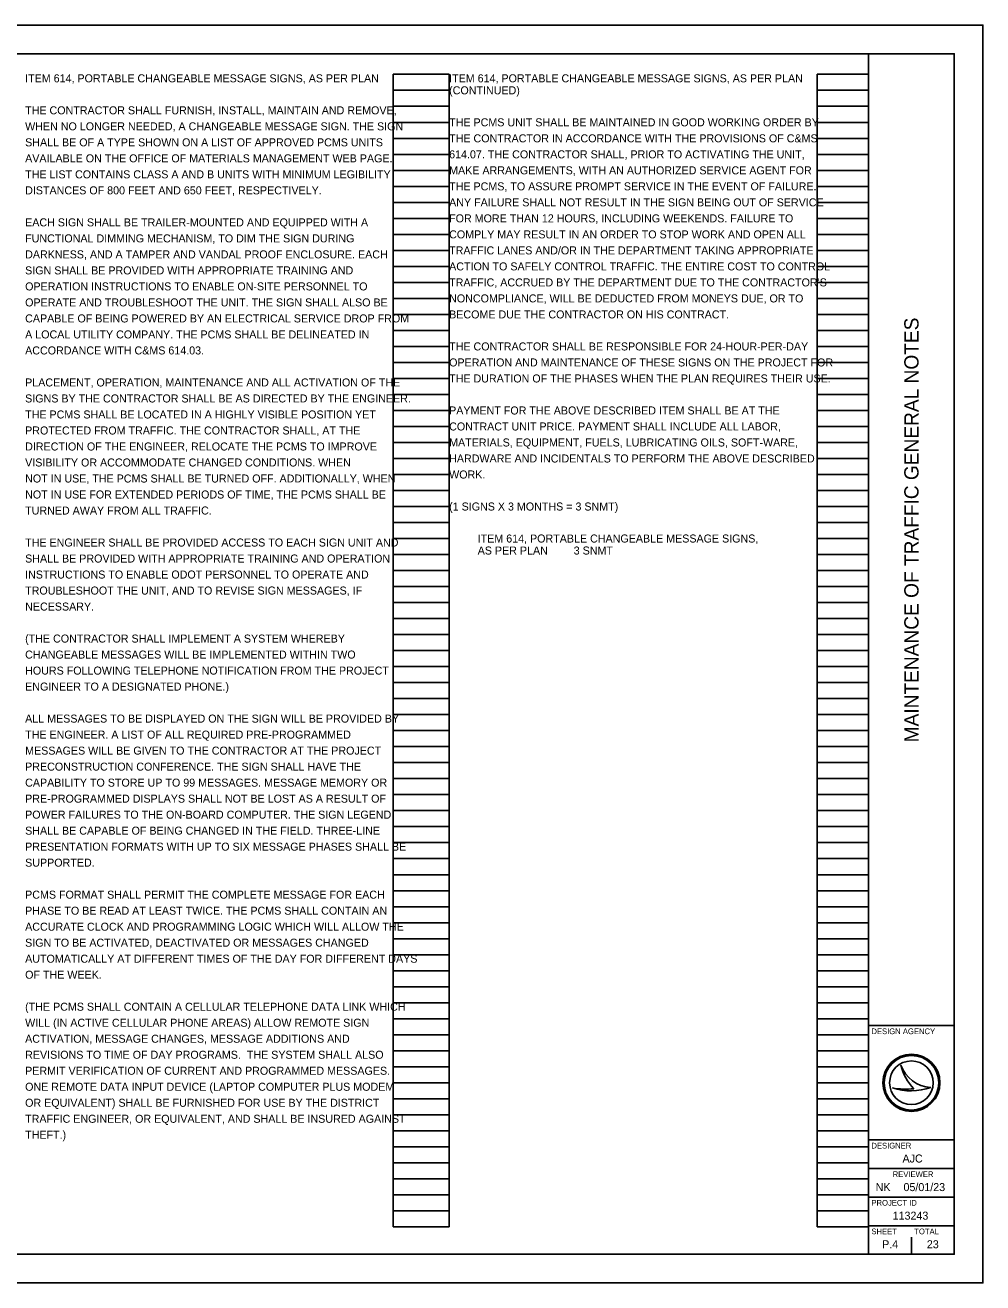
# Model space of a CAD drawing. Extents: x 0 to 34, y 0 to 22.
# Drawn here: x 17.24 to 34, y 0 to 22 of the extents above; entities that cross this region are included whole.
import ezdxf

# ---------------------------------------------------------------- set-up
doc = ezdxf.new("R2010")
doc.units = 0
for name, color, linetype in [('SH_Border', 7, 'Continuous'), ('SH_Cut_Line', 7, 'Continuous'), ('SH_Data', 7, 'Continuous'), ('SH_Text', 7, 'Continuous')]:
    doc.layers.add(name, color=color, linetype=linetype)

msp = doc.modelspace()

# ---------------------------------------------------------------- linework, layer by layer
at = {"layer": 'SH_Border'}
for p, q in [((32, 0.5), (32, 21.5)), ((32, 4.5), (33.5, 4.5)), ((32, 2.5), (33.5, 2.5)), ((32, 2), (33.5, 2)), ((32, 1.5), (33.5, 1.5)), ((32, 1), (33.5, 1))]:
    msp.add_line(p, q, dxfattribs=at)
msp.add_lwpolyline([(1.5, 21.5), (33.5, 21.5), (33.5, 0.5), (1.5, 0.5)], close=True, dxfattribs=at)
at = {"layer": 'SH_Cut_Line'}
msp.add_lwpolyline([(0, 0), (34, 0), (34, 22), (0, 22)], close=True, dxfattribs=at)
at = {"layer": 'SH_Data'}
for p, q in [((23.68, 0.98), (23.68, 21.14)), ((23.68, 21.14), (24.66, 21.14)), ((24.66, 0.98), (24.66, 21.14)), ((31.1, 0.98), (31.1, 21.14)), ((31.1, 21.14), (32, 21.14)), ((32, 0.98), (32, 21.14)), ((23.68, 20.86), (24.66, 20.86)), ((31.1, 20.86), (32, 20.86)), ((23.68, 20.58), (24.66, 20.58)), ((31.1, 20.58), (32, 20.58)), ((23.68, 20.3), (24.66, 20.3)), ((31.1, 20.3), (32, 20.3)), ((23.68, 20.02), (24.66, 20.02)), ((31.1, 20.02), (32, 20.02)), ((23.68, 19.74), (24.66, 19.74)), ((31.1, 19.74), (32, 19.74)), ((23.68, 19.46), (24.66, 19.46)), ((31.1, 19.46), (32, 19.46)), ((23.68, 19.18), (24.66, 19.18)), ((31.1, 19.18), (32, 19.18)), ((23.68, 18.9), (24.66, 18.9)), ((31.1, 18.9), (32, 18.9)), ((23.68, 18.62), (24.66, 18.62)), ((31.1, 18.62), (32, 18.62)), ((23.68, 18.34), (24.66, 18.34)), ((31.1, 18.34), (32, 18.34)), ((23.68, 18.06), (24.66, 18.06)), ((31.1, 18.06), (32, 18.06)), ((23.68, 17.78), (24.66, 17.78)), ((31.1, 17.78), (32, 17.78)), ((23.68, 17.5), (24.66, 17.5)), ((31.1, 17.5), (32, 17.5)), ((23.68, 17.22), (24.66, 17.22)), ((31.1, 17.22), (32, 17.22)), ((23.68, 16.94), (24.66, 16.94)), ((31.1, 16.94), (32, 16.94)), ((23.68, 16.66), (24.66, 16.66)), ((31.1, 16.66), (32, 16.66)), ((23.68, 16.38), (24.66, 16.38)), ((31.1, 16.38), (32, 16.38)), ((23.68, 16.1), (24.66, 16.1)), ((31.1, 16.1), (32, 16.1)), ((23.68, 15.82), (24.66, 15.82)), ((31.1, 15.82), (32, 15.82)), ((23.68, 15.54), (24.66, 15.54)), ((31.1, 15.54), (32, 15.54)), ((23.68, 15.26), (24.66, 15.26)), ((31.1, 15.26), (32, 15.26)), ((23.68, 14.98), (24.66, 14.98)), ((31.1, 14.98), (32, 14.98)), ((23.68, 14.7), (24.66, 14.7)), ((31.1, 14.7), (32, 14.7)), ((23.68, 14.42), (24.66, 14.42)), ((31.1, 14.42), (32, 14.42)), ((23.68, 14.14), (24.66, 14.14)), ((31.1, 14.14), (32, 14.14)), ((23.68, 13.86), (24.66, 13.86)), ((31.1, 13.86), (32, 13.86)), ((23.68, 13.58), (24.66, 13.58)), ((31.1, 13.58), (32, 13.58)), ((23.68, 13.3), (24.66, 13.3)), ((31.1, 13.3), (32, 13.3)), ((23.68, 13.02), (24.66, 13.02)), ((31.1, 13.02), (32, 13.02)), ((23.68, 12.74), (24.66, 12.74)), ((31.1, 12.74), (32, 12.74)), ((23.68, 12.46), (24.66, 12.46)), ((31.1, 12.46), (32, 12.46)), ((23.68, 12.18), (24.66, 12.18)), ((31.1, 12.18), (32, 12.18)), ((23.68, 11.9), (24.66, 11.9)), ((31.1, 11.9), (32, 11.9)), ((23.68, 11.62), (24.66, 11.62)), ((31.1, 11.62), (32, 11.62)), ((23.68, 11.34), (24.66, 11.34)), ((31.1, 11.34), (32, 11.34)), ((23.68, 11.06), (24.66, 11.06)), ((31.1, 11.06), (32, 11.06)), ((23.68, 10.78), (24.66, 10.78)), ((31.1, 10.78), (32, 10.78)), ((23.68, 10.5), (24.66, 10.5)), ((31.1, 10.5), (32, 10.5)), ((23.68, 10.22), (24.66, 10.22)), ((31.1, 10.22), (32, 10.22)), ((23.68, 9.94), (24.66, 9.94)), ((31.1, 9.94), (32, 9.94)), ((23.68, 9.66), (24.66, 9.66)), ((31.1, 9.66), (32, 9.66)), ((23.68, 9.38), (24.66, 9.38)), ((31.1, 9.38), (32, 9.38)), ((23.68, 9.1), (24.66, 9.1)), ((31.1, 9.1), (32, 9.1)), ((23.68, 8.82), (24.66, 8.82)), ((31.1, 8.82), (32, 8.82)), ((23.68, 8.54), (24.66, 8.54)), ((31.1, 8.54), (32, 8.54)), ((23.68, 8.26), (24.66, 8.26)), ((31.1, 8.26), (32, 8.26)), ((23.68, 7.98), (24.66, 7.98)), ((31.1, 7.98), (32, 7.98)), ((23.68, 7.7), (24.66, 7.7)), ((31.1, 7.7), (32, 7.7)), ((23.68, 7.42), (24.66, 7.42)), ((31.1, 7.42), (32, 7.42)), ((23.68, 7.14), (24.66, 7.14)), ((31.1, 7.14), (32, 7.14)), ((23.68, 6.86), (24.66, 6.86)), ((31.1, 6.86), (32, 6.86)), ((23.68, 6.58), (24.66, 6.58)), ((31.1, 6.58), (32, 6.58)), ((23.68, 6.3), (24.66, 6.3)), ((31.1, 6.3), (32, 6.3)), ((23.68, 6.02), (24.66, 6.02)), ((31.1, 6.02), (32, 6.02)), ((23.68, 5.74), (24.66, 5.74)), ((31.1, 5.74), (32, 5.74)), ((23.68, 5.46), (24.66, 5.46)), ((31.1, 5.46), (32, 5.46)), ((23.68, 5.18), (24.66, 5.18)), ((31.1, 5.18), (32, 5.18)), ((23.68, 4.9), (24.66, 4.9)), ((31.1, 4.9), (32, 4.9)), ((23.68, 4.62), (24.66, 4.62)), ((31.1, 4.62), (32, 4.62)), ((23.68, 4.34), (24.66, 4.34)), ((31.1, 4.34), (32, 4.34)), ((23.68, 4.06), (24.66, 4.06)), ((31.1, 4.06), (32, 4.06)), ((23.68, 3.78), (24.66, 3.78)), ((31.1, 3.78), (32, 3.78)), ((32.567, 3.81), (32.567, 3.81)), ((23.68, 3.5), (24.66, 3.5)), ((31.1, 3.5), (32, 3.5)), ((32.417, 3.41), (32.417, 3.41)), ((32.75, 3.5), (32.75, 3.5)), ((33.087, 3.419), (33.087, 3.419)), ((23.68, 3.22), (24.66, 3.22)), ((31.1, 3.22), (32, 3.22)), ((23.68, 2.94), (24.66, 2.94)), ((31.1, 2.94), (32, 2.94)), ((23.68, 2.66), (24.66, 2.66)), ((31.1, 2.66), (32, 2.66)), ((23.68, 2.38), (24.66, 2.38)), ((31.1, 2.38), (32, 2.38)), ((23.68, 2.1), (24.66, 2.1)), ((31.1, 2.1), (32, 2.1)), ((23.68, 1.82), (24.66, 1.82)), ((31.1, 1.82), (32, 1.82)), ((23.68, 1.54), (24.66, 1.54)), ((31.1, 1.54), (32, 1.54)), ((23.68, 1.26), (24.66, 1.26)), ((31.1, 1.26), (32, 1.26)), ((23.68, 0.98), (24.66, 0.98)), ((31.1, 0.98), (32, 0.98)), ((32.375, 0.675), (32.375, 0.675)), ((32.75, 0.5), (32.75, 0.8))]:
    msp.add_line(p, q, dxfattribs=at)
for radius in [0.5, 0.477, 0.477, 0.382]:
    msp.add_circle((32.75, 3.5), radius, dxfattribs=at)
for centre, radius, start, end in [((33.116, 3.998), 0.58, 198.9257, 198.9319), ((33.347, 3.97), 0.796, 191.6379, 191.6421), ((33.116, 3.998), 0.58, 198.9319, 267.1657), ((33.347, 3.97), 0.796, 191.6421, 226.0947), ((32.739, 4.37), 1.013, 251.4576, 290.0832), ((32.648, 4.654), 1.266, 259.4964, 259.4995), ((32.739, 4.37), 1.013, 251.4527, 251.4576), ((32.648, 4.654), 1.266, 259.4995, 276.6672)]:
    msp.add_arc(centre, radius, start, end, dxfattribs=at)

# ---------------------------------------------------------------- texts
msp.add_text('MAINTENANCE OF TRAFFIC GENERAL NOTES', height=0.25, rotation=90, dxfattribs=at).set_placement((32.875, 9.455))
for s, height, p in [('DESIGN AGENCY', 0.1, (32.05, 4.35)), ('DESIGNER', 0.1, (32.05, 2.35)), ('AJC', 0.14, (32.594, 2.105)), ('REVIEWER', 0.1, (32.422, 1.85)), ('NK', 0.14, (32.124, 1.605)), ('05/01/23', 0.14, (32.611, 1.605)), ('PROJECT ID', 0.1, (32.05, 1.35)), ('113243', 0.14, (32.421, 1.105)), ('SHEET', 0.1, (32.05, 0.85)), ('TOTAL', 0.1, (32.8, 0.85)), ('P.4', 0.14, (32.237, 0.605)), ('23', 0.14, (33.02, 0.605))]:
    msp.add_text(s, height=height, dxfattribs=at).set_placement(p)
at = {"layer": 'SH_Text'}
for s, p in [('ITEM 614, PORTABLE CHANGEABLE MESSAGE SIGNS, AS PER PLAN', (17.24, 21)), ('ITEM 614, PORTABLE CHANGEABLE MESSAGE SIGNS, AS PER PLAN', (24.66, 21)), ('(CONTINUED)', (24.66, 20.79)), ('THE CONTRACTOR SHALL FURNISH, INSTALL, MAINTAIN AND REMOVE, ', (17.24, 20.44)), ('WHEN NO LONGER NEEDED, A CHANGEABLE MESSAGE SIGN. THE SIGN ', (17.24, 20.16)), ('THE PCMS UNIT SHALL BE MAINTAINED IN GOOD WORKING ORDER BY ', (24.66, 20.23)), ('SHALL BE OF A TYPE SHOWN ON A LIST OF APPROVED PCMS UNITS ', (17.24, 19.88)), ('THE CONTRACTOR IN ACCORDANCE WITH THE PROVISIONS OF C&MS ', (24.66, 19.95)), ('614.07. THE CONTRACTOR SHALL, PRIOR TO ACTIVATING THE UNIT, ', (24.66, 19.67)), ('AVAILABLE ON THE OFFICE OF MATERIALS MANAGEMENT WEB PAGE. ', (17.24, 19.6)), ('THE LIST CONTAINS CLASS A AND B UNITS WITH MINIMUM LEGIBILITY ', (17.24, 19.32)), ('MAKE ARRANGEMENTS, WITH AN AUTHORIZED SERVICE AGENT FOR ', (24.66, 19.39)), ('DISTANCES OF 800 FEET AND 650 FEET, RESPECTIVELY.', (17.24, 19.04)), ('THE PCMS, TO ASSURE PROMPT SERVICE IN THE EVENT OF FAILURE. ', (24.66, 19.11)), ('ANY FAILURE SHALL NOT RESULT IN THE SIGN BEING OUT OF SERVICE ', (24.66, 18.83)), ('EACH SIGN SHALL BE TRAILER-MOUNTED AND EQUIPPED WITH A ', (17.24, 18.48)), ('FOR MORE THAN 12 HOURS, INCLUDING WEEKENDS. FAILURE TO ', (24.66, 18.55)), ('FUNCTIONAL DIMMING MECHANISM, TO DIM THE SIGN DURING ', (17.24, 18.2)), ('COMPLY MAY RESULT IN AN ORDER TO STOP WORK AND OPEN ALL ', (24.66, 18.27)), ('DARKNESS, AND A TAMPER AND VANDAL PROOF ENCLOSURE. EACH ', (17.24, 17.92)), ('TRAFFIC LANES AND/OR IN THE DEPARTMENT TAKING APPROPRIATE ', (24.66, 17.99)), ('ACTION TO SAFELY CONTROL TRAFFIC. THE ENTIRE COST TO CONTROL ', (24.66, 17.71)), ('SIGN SHALL BE PROVIDED WITH APPROPRIATE TRAINING AND ', (17.24, 17.64)), ('OPERATION INSTRUCTIONS TO ENABLE ON-SITE PERSONNEL TO ', (17.24, 17.36)), ("TRAFFIC, ACCRUED BY THE DEPARTMENT DUE TO THE CONTRACTOR'S", (24.66, 17.43)), ('OPERATE AND TROUBLESHOOT THE UNIT. THE SIGN SHALL ALSO BE ', (17.24, 17.08)), ('NONCOMPLIANCE, WILL BE DEDUCTED FROM MONEYS DUE, OR TO ', (24.66, 17.15)), ('CAPABLE OF BEING POWERED BY AN ELECTRICAL SERVICE DROP FROM ', (17.24, 16.8)), ('BECOME DUE THE CONTRACTOR ON HIS CONTRACT.', (24.66, 16.87)), ('A LOCAL UTILITY COMPANY. THE PCMS SHALL BE DELINEATED IN ', (17.24, 16.52)), ('ACCORDANCE WITH C&MS 614.03.', (17.24, 16.24)), ('THE CONTRACTOR SHALL BE RESPONSIBLE FOR 24-HOUR-PER-DAY ', (24.66, 16.31)), ('OPERATION AND MAINTENANCE OF THESE SIGNS ON THE PROJECT FOR ', (24.66, 16.03)), ('THE DURATION OF THE PHASES WHEN THE PLAN REQUIRES THEIR USE.', (24.66, 15.75)), ('PLACEMENT, OPERATION, MAINTENANCE AND ALL ACTIVATION OF THE ', (17.24, 15.68)), ('SIGNS BY THE CONTRACTOR SHALL BE AS DIRECTED BY THE ENGINEER. ', (17.24, 15.4)), ('THE PCMS SHALL BE LOCATED IN A HIGHLY VISIBLE POSITION YET ', (17.24, 15.12)), ('PAYMENT FOR THE ABOVE DESCRIBED ITEM SHALL BE AT THE ', (24.66, 15.19)), ('PROTECTED FROM TRAFFIC. THE CONTRACTOR SHALL, AT THE ', (17.24, 14.84)), ('CONTRACT UNIT PRICE. PAYMENT SHALL INCLUDE ALL LABOR, ', (24.66, 14.91)), ('MATERIALS, EQUIPMENT, FUELS, LUBRICATING OILS, SOFT-WARE, ', (24.66, 14.63)), ('DIRECTION OF THE ENGINEER, RELOCATE THE PCMS TO IMPROVE', (17.24, 14.56)), ('VISIBILITY OR ACCOMMODATE CHANGED CONDITIONS. WHEN', (17.24, 14.28)), ('HARDWARE AND INCIDENTALS TO PERFORM THE ABOVE DESCRIBED ', (24.66, 14.35)), ('NOT IN USE, THE PCMS SHALL BE TURNED OFF. ADDITIONALLY, WHEN ', (17.24, 14)), ('WORK.', (24.66, 14.07)), ('NOT IN USE FOR EXTENDED PERIODS OF TIME, THE PCMS SHALL BE ', (17.24, 13.72)), ('(1 SIGNS X 3 MONTHS = 3 SNMT)', (24.66, 13.51)), ('TURNED AWAY FROM ALL TRAFFIC.', (17.24, 13.44)), ('THE ENGINEER SHALL BE PROVIDED ACCESS TO EACH SIGN UNIT AND ', (17.24, 12.88)), ('ITEM 614, PORTABLE CHANGEABLE MESSAGE SIGNS, ', (25.16, 12.95)), ('AS PER PLAN', (25.16, 12.74)), ('3 SNMT', (26.84, 12.74)), ('SHALL BE PROVIDED WITH APPROPRIATE TRAINING AND OPERATION ', (17.24, 12.6)), ('INSTRUCTIONS TO ENABLE ODOT PERSONNEL TO OPERATE AND ', (17.24, 12.32)), ('TROUBLESHOOT THE UNIT, AND TO REVISE SIGN MESSAGES, IF ', (17.24, 12.04)), ('NECESSARY.', (17.24, 11.76)), ('(THE CONTRACTOR SHALL IMPLEMENT A SYSTEM WHEREBY ', (17.24, 11.2)), ('CHANGEABLE MESSAGES WILL BE IMPLEMENTED WITHIN TWO', (17.24, 10.92)), ('HOURS FOLLOWING TELEPHONE NOTIFICATION FROM THE PROJECT ', (17.24, 10.64)), ('ENGINEER TO A DESIGNATED PHONE.)', (17.24, 10.36)), ('ALL MESSAGES TO BE DISPLAYED ON THE SIGN WILL BE PROVIDED BY ', (17.24, 9.8)), ('THE ENGINEER. A LIST OF ALL REQUIRED PRE-PROGRAMMED ', (17.24, 9.52)), ('MESSAGES WILL BE GIVEN TO THE CONTRACTOR AT THE PROJECT ', (17.24, 9.24)), ('PRECONSTRUCTION CONFERENCE. THE SIGN SHALL HAVE THE ', (17.24, 8.96)), ('CAPABILITY TO STORE UP TO 99 MESSAGES. MESSAGE MEMORY OR', (17.24, 8.68)), ('PRE-PROGRAMMED DISPLAYS SHALL NOT BE LOST AS A RESULT OF ', (17.24, 8.4)), ('POWER FAILURES TO THE ON-BOARD COMPUTER. THE SIGN LEGEND ', (17.24, 8.12)), ('SHALL BE CAPABLE OF BEING CHANGED IN THE FIELD. THREE-LINE ', (17.24, 7.84)), ('PRESENTATION FORMATS WITH UP TO SIX MESSAGE PHASES SHALL BE', (17.24, 7.56)), ('SUPPORTED.  ', (17.24, 7.28)), ('PCMS FORMAT SHALL PERMIT THE COMPLETE MESSAGE FOR EACH ', (17.24, 6.72)), ('PHASE TO BE READ AT LEAST TWICE. THE PCMS SHALL CONTAIN AN ', (17.24, 6.44)), ('ACCURATE CLOCK AND PROGRAMMING LOGIC WHICH WILL ALLOW THE ', (17.24, 6.16)), ('SIGN TO BE ACTIVATED, DEACTIVATED OR MESSAGES CHANGED', (17.24, 5.88)), ('AUTOMATICALLY AT DIFFERENT TIMES OF THE DAY FOR DIFFERENT DAYS ', (17.24, 5.6)), ('OF THE WEEK.', (17.24, 5.32)), ('(THE PCMS SHALL CONTAIN A CELLULAR TELEPHONE DATA LINK WHICH ', (17.24, 4.76)), ('WILL (IN ACTIVE CELLULAR PHONE AREAS) ALLOW REMOTE SIGN ', (17.24, 4.48)), ('ACTIVATION, MESSAGE CHANGES, MESSAGE ADDITIONS AND ', (17.24, 4.2)), ('REVISIONS TO TIME OF DAY PROGRAMS.  THE SYSTEM SHALL ALSO ', (17.24, 3.92)), ('PERMIT VERIFICATION OF CURRENT AND PROGRAMMED MESSAGES. ', (17.24, 3.64)), ('ONE REMOTE DATA INPUT DEVICE (LAPTOP COMPUTER PLUS MODEM ', (17.24, 3.36)), ('OR EQUIVALENT) SHALL BE FURNISHED FOR USE BY THE DISTRICT ', (17.24, 3.08)), ('TRAFFIC ENGINEER, OR EQUIVALENT, AND SHALL BE INSURED AGAINST ', (17.24, 2.8)), ('THEFT.)', (17.24, 2.52))]:
    msp.add_text(s, height=0.14, dxfattribs=at).set_placement(p)

doc.saveas('drawing.dxf')
